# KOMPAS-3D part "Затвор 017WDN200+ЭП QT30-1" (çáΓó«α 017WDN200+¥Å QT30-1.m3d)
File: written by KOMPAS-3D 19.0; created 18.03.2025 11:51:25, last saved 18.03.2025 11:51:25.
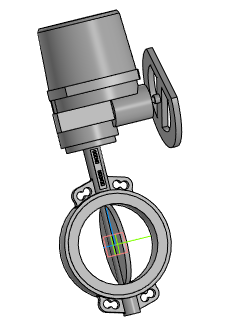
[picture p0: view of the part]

Document properties: Полное имя файла: Затвор 017WDN200+ЭП QT30-1.a3d

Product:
- Part/product: Затвор 017WDN200+ЭП QT30-1
    Масса: 98.2984

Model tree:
1. Операция без истории:1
